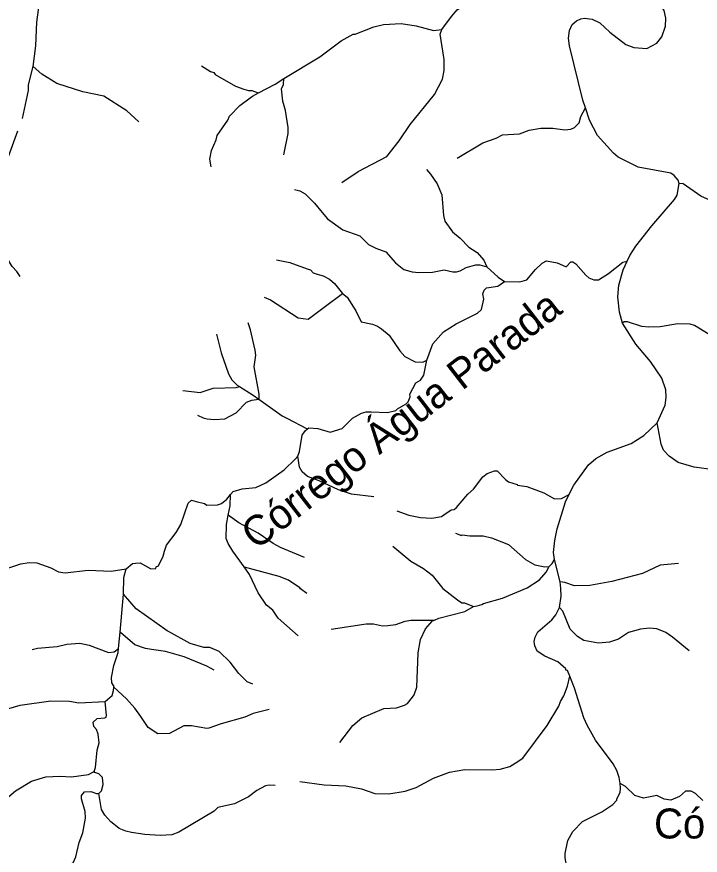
# Model space of a CAD drawing. Extents: x 393 to 446.6, y 8175.5 to 8231.
# Drawn here: x 408.07 to 412.63, y 8185.27 to 8190.87 of the extents above; entities that cross this region are included whole.
import ezdxf
from ezdxf.enums import TextEntityAlignment as Align

# ---------------------------------------------------------------- set-up
doc = ezdxf.new("R2010")
doc.units = 0
doc.header["$LTSCALE"] = 0.064
doc.linetypes.add('LONG_DASHED', pattern=[7.5, 6, -1.5])
doc.layers.add('61', color=7, linetype='Continuous')
doc.layers.add('7', color=7, linetype='Continuous', lineweight=25)
doc.layers.add('9', color=7, linetype='LONG_DASHED', lineweight=25)

msp = doc.modelspace()

# ---------------------------------------------------------------- linework, layer by layer
at = {"layer": '7'}
msp.add_line((411.6931, 8187.0939), (411.6559, 8187.2417), dxfattribs=at)
for points in [[(411.8626, 8190.2594), (411.8458, 8190.3093), (411.757, 8190.6727), (411.7505, 8190.7244), (411.757, 8190.7761), (411.7748, 8190.8148), (411.8039, 8190.839), (411.8329, 8190.8536), (411.8555, 8190.8568), (411.9072, 8190.8519), (411.9589, 8190.8277), (412.025, 8190.7647), (412.1333, 8190.6808), (412.1849, 8190.6614), (412.2721, 8190.6549), (412.3399, 8190.6904), (412.3739, 8190.7325), (412.3981, 8190.8051), (412.3997, 8190.8568), (412.3884, 8190.9085), (412.3604, 8190.9515)], [(411.0056, 8189.9223), (411.1773, 8190.0251), (411.2677, 8190.0574), (411.3081, 8190.0784), (411.4228, 8190.0849), (411.4874, 8190.1091), (411.5649, 8190.122), (411.6456, 8190.122), (411.7263, 8190.1123), (411.7651, 8190.1156), (411.7893, 8190.1285), (411.82, 8190.1592), (411.8313, 8190.2012), (411.8626, 8190.2594)], [(412.4884, 8189.7544), (412.4826, 8189.7765), (412.4558, 8189.8073), (412.4336, 8189.8217), (412.214, 8189.8637), (412.0816, 8189.9299), (412.0493, 8189.9557), (411.9427, 8190.0752), (411.891, 8190.1754), (411.8626, 8190.2594)], [(412.1415, 8189.2349), (412.1594, 8189.2722), (412.1995, 8189.3357), (412.306, 8189.4697), (412.4578, 8189.6457), (412.4756, 8189.6748), (412.4884, 8189.7544)], [(412.1106, 8188.8205), (412.0896, 8188.8932), (412.0784, 8188.9966), (412.0864, 8189.0741), (412.1139, 8189.1774), (412.1415, 8189.2349)], [(413.0772, 8188.4153), (412.9907, 8188.4734), (412.9229, 8188.5412), (412.8599, 8188.5912), (412.7436, 8188.7124), (412.7081, 8188.7398), (412.6888, 8188.7446), (412.5919, 8188.8044), (412.5628, 8188.8141), (412.4788, 8188.8157), (412.3626, 8188.7963), (412.2851, 8188.7947), (412.2398, 8188.7995), (412.1432, 8188.83), (412.1222, 8188.83), (412.1106, 8188.8205)], [(412.3416, 8188.1545), (412.3949, 8188.2731), (412.4029, 8188.3248), (412.3997, 8188.3765), (412.3723, 8188.454), (412.2964, 8188.5638), (412.1995, 8188.6801), (412.1106, 8188.8205)], [(411.7528, 8187.6744), (411.7845, 8187.7386), (411.883, 8187.8743), (411.9314, 8187.9162), (412.0073, 8187.9599), (412.1688, 8188.018), (412.2527, 8188.0697), (412.3416, 8188.1545)], [(413.5273, 8187.5871), (413.4138, 8187.6337), (413.2992, 8187.6692), (413.1377, 8187.7015), (413.0699, 8187.7079), (413.0246, 8187.7192), (413.002, 8187.7176), (412.9568, 8187.7289), (412.7663, 8187.8258), (412.721, 8187.8403), (412.5886, 8187.8597), (412.4816, 8187.8904), (412.4223, 8187.9324), (412.3835, 8187.9728), (412.3674, 8188.0115), (412.3416, 8188.1545)], [(410.6046, 8187.5674), (410.6832, 8187.5384), (410.7607, 8187.5238), (410.8382, 8187.5174), (410.9028, 8187.5303), (410.9175, 8187.5405), (410.9658, 8187.5739), (410.9867, 8187.5771), (411.0013, 8187.59), (411.0772, 8187.6789), (411.116, 8187.7128), (411.1789, 8187.7952), (411.2064, 8187.8177), (411.2548, 8187.8339), (411.2742, 8187.8355), (411.3291, 8187.7758), (411.3501, 8187.7612), (411.4066, 8187.7434), (411.4082, 8187.7386), (411.4712, 8187.7289), (411.5842, 8187.6869), (411.6553, 8187.6482), (411.7037, 8187.6498), (411.7505, 8187.6732), (411.7528, 8187.6744)], [(411.6559, 8187.2417), (411.65, 8187.2894), (411.6585, 8187.3689), (411.6747, 8187.4464), (411.7296, 8187.6272), (411.7528, 8187.6744)], [(410.9946, 8187.4174), (411.0354, 8187.4034), (411.04, 8187.4076), (411.0901, 8187.4011), (411.1805, 8187.4011), (411.2354, 8187.3866), (411.3485, 8187.3414), (411.4631, 8187.2429), (411.5245, 8187.2057), (411.5907, 8187.1928), (411.6213, 8187.1963)], [(410.5764, 8187.331), (410.6977, 8187.2316), (410.7814, 8187.1821), (410.8398, 8187.1379), (410.9109, 8187.0491), (411.0077, 8186.9732), (411.0384, 8186.9538), (411.0562, 8186.9522), (411.1159, 8186.9273)], [(411.6213, 8187.1963), (411.6411, 8187.2149), (411.6559, 8187.2417)], [(411.1159, 8186.9273), (411.1389, 8186.9331), (411.1718, 8186.9413), (411.1821, 8186.949), (411.3097, 8186.9829), (411.4744, 8187.0539), (411.5568, 8187.1072), (411.6004, 8187.1573), (411.6213, 8187.1963)], [(412.4838, 8187.2162), (412.3609, 8187.2041), (412.2431, 8187.1492), (412.0396, 8187.0943), (411.8911, 8187.0685), (411.7909, 8187.0668), (411.7263, 8187.0894), (411.6931, 8187.0939)], [(411.6906, 8186.9226), (411.7005, 8186.9975), (411.6989, 8187.0491), (411.6931, 8187.0939)], [(410.8544, 8186.8375), (410.885, 8186.8505), (411.0578, 8186.8957), (411.1159, 8186.9273)], [(411.7581, 8186.4624), (411.7427, 8186.5012), (411.7328, 8186.5033), (411.7328, 8186.513), (411.6795, 8186.5598), (411.5907, 8186.597), (411.5406, 8186.6308), (411.5245, 8186.6648), (411.5212, 8186.6939), (411.5261, 8186.7229), (411.5454, 8186.7584), (411.6391, 8186.8392), (411.665, 8186.8731), (411.6906, 8186.9226)], [(412.5547, 8186.6325), (412.4433, 8186.7245), (412.3997, 8186.7536), (412.34, 8186.7794), (412.2915, 8186.7843), (412.2302, 8186.7778), (412.1494, 8186.7536), (412.0837, 8186.7103), (412.0235, 8186.689), (411.9492, 8186.6842), (411.8523, 8186.7003), (411.8103, 8186.7277), (411.7618, 8186.7778), (411.7118, 8186.8973), (411.6906, 8186.9226)], [(410.1642, 8186.7769), (410.399, 8186.8133), (410.4474, 8186.8133), (410.5088, 8186.7988), (410.5443, 8186.8004), (410.596, 8186.8085), (410.659, 8186.8311), (410.6961, 8186.8375), (410.8544, 8186.8375)], [(410.222, 8186.019), (410.3101, 8186.1335), (410.3699, 8186.1852), (410.5168, 8186.2481), (410.6008, 8186.2514), (410.6541, 8186.2691), (410.6751, 8186.2804), (410.709, 8186.3224), (410.7203, 8186.3386), (410.7364, 8186.3903), (410.7461, 8186.6164), (410.7464, 8186.6184), (410.7607, 8186.7068), (410.7946, 8186.7794), (410.8421, 8186.8323), (410.8544, 8186.8375)], [(409.9559, 8185.7602), (410.118, 8185.7363), (410.2633, 8185.7314), (410.3667, 8185.7104), (410.4571, 8185.6797), (410.5508, 8185.6765), (410.659, 8185.6943), (410.7316, 8185.7201), (410.8479, 8185.7815), (410.9545, 8185.8219), (411.0578, 8185.8396), (411.2419, 8185.838), (411.2936, 8185.8428), (411.3582, 8185.859), (411.3933, 8185.8818), (411.4454, 8185.9155), (411.6084, 8186.1335), (411.6859, 8186.2627), (411.6956, 8186.2934), (411.7182, 8186.3322), (411.7425, 8186.3967), (411.7581, 8186.4624)], [(412.0939, 8185.7472), (412.0891, 8185.7866), (412.0719, 8185.8332), (412.0477, 8185.8768), (411.9298, 8186.0366), (411.8733, 8186.1352), (411.8523, 8186.1836), (411.7893, 8186.3838), (411.7581, 8186.4624)], [(411.8612, 8184.6542), (411.8344, 8184.6949), (411.8006, 8184.8207), (411.7812, 8185.0339), (411.7457, 8185.1534), (411.7279, 8185.2502), (411.7279, 8185.2793), (411.7457, 8185.3665), (411.778, 8185.4246), (411.8426, 8185.4924), (411.9718, 8185.557), (412.046, 8185.6055), (412.0719, 8185.6345), (412.0719, 8185.6442), (412.0945, 8185.6862), (412.0977, 8185.7153), (412.0939, 8185.7472)], [(412.6468, 8185.6329), (412.5967, 8185.6797), (412.5693, 8185.6959), (412.5305, 8185.6943), (412.4901, 8185.6588), (412.4336, 8185.6345), (412.3884, 8185.6426), (412.34, 8185.6652), (412.2511, 8185.6475), (412.193, 8185.6652), (412.13, 8185.725), (412.095, 8185.7465), (412.0939, 8185.7472)]]:
    msp.add_lwpolyline(points, dxfattribs=at)
at = {"layer": '9'}
for p, q in [((408.7562, 8186.7561), (408.7795, 8187.0107)), ((408.7463, 8186.6484), (408.7562, 8186.7561))]:
    msp.add_line(p, q, dxfattribs=at)
for points in [[(410.9033, 8190.7814), (410.9675, 8190.8689), (411.0061, 8190.9133), (411.0368, 8190.9359), (411.0788, 8190.9925), (411.103, 8191.1297), (411.1498, 8191.1684), (411.1691, 8191.2413), (411.1854, 8191.2705), (411.2519, 8191.3416), (411.2718, 8191.3789), (411.2887, 8191.4349), (411.2952, 8191.5189), (411.3722, 8191.6951)], [(408.1751, 8190.5341), (408.1756, 8190.536), (408.1931, 8190.6736), (408.2012, 8190.831), (408.227, 8191.0247), (408.2481, 8191.1232), (408.2635, 8191.1731), (408.2884, 8191.254), (408.3385, 8191.3816), (408.4128, 8191.4962), (408.4692, 8191.5543), (408.4694, 8191.5545)], [(409.85, 8190.4547), (410.0889, 8190.5984), (410.2326, 8190.7066), (410.3118, 8190.7518), (410.3247, 8190.7518), (410.4507, 8190.8002), (410.5152, 8190.8148), (410.6315, 8190.8229), (410.7316, 8190.8067), (410.8479, 8190.776), (410.9033, 8190.7814)], [(410.2356, 8189.7609), (410.3457, 8189.8346), (410.5362, 8189.9347), (410.6202, 8190.0381), (410.6928, 8190.1479), (410.856, 8190.3481), (410.9076, 8190.4499), (410.9189, 8190.508), (410.9189, 8190.5823), (410.8931, 8190.7502), (410.9033, 8190.7814)], [(408.0879, 8189.1316), (408.0669, 8189.1655), (408.0365, 8189.1984), (407.9994, 8189.2598), (407.9654, 8189.3324), (407.9251, 8189.4616), (407.9105, 8189.6102), (407.9219, 8189.6812), (407.9396, 8189.7442), (408.1043, 8190.1883), (408.1447, 8190.3756), (408.1447, 8190.4127), (408.1751, 8190.5341)], [(408.8814, 8190.1645), (408.8019, 8190.2399), (408.6485, 8190.3368), (408.508, 8190.3659), (408.3336, 8190.4224), (408.2335, 8190.4837), (408.1751, 8190.5341)], [(409.3005, 8190.5392), (409.3589, 8190.5007), (409.3817, 8190.4951), (409.3914, 8190.4805), (409.527, 8190.403), (409.582, 8190.3846), (409.6142, 8190.3739), (409.6352, 8190.3739), (409.6773, 8190.3599), (409.6811, 8190.3586)], [(409.6811, 8190.3586), (409.7918, 8190.4175), (409.85, 8190.4547)], [(409.8483, 8189.9443), (409.8508, 8189.9562), (409.879, 8190.0882), (409.879, 8190.1269), (409.8612, 8190.24), (409.8419, 8190.3029), (409.8338, 8190.3853), (409.8461, 8190.4141), (409.85, 8190.4547)], [(409.3637, 8189.8656), (409.3558, 8189.917), (409.3671, 8189.9735), (409.3978, 8190.0445), (409.4043, 8190.0736), (409.4753, 8190.177), (409.4866, 8190.2028), (409.5544, 8190.2738), (409.6239, 8190.325), (409.64, 8190.3368), (409.6811, 8190.3586)], [(410.8012, 8189.8466), (410.8285, 8189.8168), (410.8737, 8189.7507), (410.9044, 8189.678), (410.9141, 8189.5391), (410.9238, 8189.502), (410.9755, 8189.4309), (411.0271, 8189.3889), (411.0836, 8189.3292), (411.1402, 8189.2921), (411.1837, 8189.2404), (411.205, 8189.1978)], [(409.921, 8189.7125), (409.9549, 8189.7044), (409.9551, 8189.7043), (409.9921, 8189.6844), (410.055, 8189.6215), (410.1046, 8189.5607), (410.1406, 8189.5165), (410.244, 8189.4438), (410.357, 8189.4035), (410.4135, 8189.347), (410.4636, 8189.3211), (410.5298, 8189.2969), (410.5944, 8189.2242), (410.6493, 8189.179), (410.7058, 8189.1628), (410.751, 8189.158), (410.8414, 8189.1612), (410.9205, 8189.1758), (410.9771, 8189.1628), (411.0029, 8189.1628), (411.0271, 8189.1693), (411.0659, 8189.1919), (411.1321, 8189.2113), (411.1579, 8189.2097), (411.205, 8189.1978)], [(413.201, 8189.6554), (413.1816, 8189.6566), (413.1151, 8189.7068), (413.0731, 8189.715), (413.0246, 8189.6899), (413.0004, 8189.6618), (412.9552, 8189.6376), (412.8761, 8189.6505), (412.826, 8189.6893), (412.8147, 8189.6893), (412.7404, 8189.6311), (412.7178, 8189.6311), (412.6339, 8189.6683), (412.5144, 8189.7522), (412.4884, 8189.7544)], [(409.8006, 8189.2444), (409.8903, 8189.2259), (410.0041, 8189.1845), (410.0276, 8189.1758), (410.0453, 8189.1564), (410.0722, 8189.1485), (410.1116, 8189.137), (410.1535, 8189.1144), (410.1874, 8189.0854), (410.2405, 8189.0195)], [(411.205, 8189.1978), (411.2809, 8189.1278), (411.3231, 8189.0993)], [(411.3231, 8189.0993), (411.4246, 8189.0958), (411.4719, 8189.1103), (411.5291, 8189.1792), (411.5746, 8189.221), (411.6036, 8189.2372), (411.6747, 8189.2226), (411.7296, 8189.1984), (411.736, 8189.1984), (411.7643, 8189.2304), (411.7795, 8189.2304), (411.7993, 8189.2176), (411.8652, 8189.1419), (411.8852, 8189.1238), (411.9178, 8189.1107), (411.9427, 8189.1112), (411.9508, 8189.1112), (412.017, 8189.1516), (412.1123, 8189.2274), (412.1415, 8189.2349)], [(410.8039, 8188.5733), (410.8436, 8188.6829), (410.9157, 8188.7624), (410.9997, 8188.8173), (411.1418, 8188.8867), (411.1692, 8188.911), (411.1837, 8188.9804), (411.1773, 8189.0159), (411.187, 8189.0417), (411.2015, 8189.0563), (411.279, 8189.0676), (411.3231, 8189.0993)], [(409.7174, 8188.9942), (409.7594, 8188.9767), (409.9452, 8188.8561), (410.0114, 8188.8463), (410.1275, 8188.9341), (410.2405, 8189.0195)], [(410.2405, 8189.0195), (410.273, 8188.9949), (410.3295, 8188.9029), (410.3651, 8188.8302), (410.4404, 8188.8133), (410.4749, 8188.8011), (410.5023, 8188.7818), (410.5524, 8188.7414), (410.6234, 8188.6349), (410.6574, 8188.5977), (410.7251, 8188.5621), (410.7769, 8188.5604), (410.8039, 8188.5733)], [(409.6826, 8188.313), (409.6836, 8188.3132), (409.6852, 8188.3474), (409.6513, 8188.5299), (409.6626, 8188.6074), (409.6578, 8188.6413), (409.6269, 8188.7762), (409.6106, 8188.8228)], [(409.4, 8188.748), (409.4317, 8188.6219), (409.4801, 8188.4831), (409.5028, 8188.4427), (409.5383, 8188.4071), (409.5537, 8188.3974)], [(410.0075, 8188.114), (410.0163, 8188.1208), (410.0764, 8188.1167), (410.1584, 8188.0923), (410.2391, 8188.1165), (410.3069, 8188.1859), (410.3667, 8188.2198), (410.399, 8188.2295), (410.4331, 8188.2279), (410.5411, 8188.223), (410.5976, 8188.2376), (410.6073, 8188.2489), (410.667, 8188.2828), (410.6799, 8188.2957), (410.6928, 8188.328), (410.6912, 8188.3474), (410.73, 8188.4217), (410.7607, 8188.4394), (410.7849, 8188.4734), (410.8039, 8188.5733)], [(409.1754, 8188.3716), (409.2896, 8188.3571), (409.3784, 8188.3861), (409.5302, 8188.391), (409.5529, 8188.3972), (409.5537, 8188.3974)], [(409.5537, 8188.3974), (409.6451, 8188.34), (409.6826, 8188.313)], [(409.272, 8188.2052), (409.3106, 8188.1875), (409.3364, 8188.1827), (409.3865, 8188.1763), (409.4559, 8188.1811), (409.5318, 8188.2214), (409.5996, 8188.2925), (409.6352, 8188.3054), (409.6826, 8188.313)], [(409.6826, 8188.313), (409.837, 8188.202), (409.8691, 8188.1855), (410.0058, 8188.1149), (410.0075, 8188.114)], [(409.9416, 8187.9318), (409.9532, 8187.9645), (409.9719, 8188.0729), (409.9918, 8188.1021), (410.0075, 8188.114)], [(409.4939, 8187.6759), (409.5108, 8187.6966), (409.5706, 8187.7144), (409.6626, 8187.7241), (409.7288, 8187.7532), (409.8516, 8187.842), (409.9258, 8187.9114), (409.9416, 8187.9318)], [(410.451, 8187.6608), (410.301, 8187.6777), (410.2133, 8187.708), (410.0841, 8187.7677), (410.0065, 8187.7961), (409.9726, 8187.8276), (409.9528, 8187.8591), (409.9416, 8187.9318)], [(408.797, 8187.1798), (408.8379, 8187.2148), (408.8585, 8187.2186), (408.8891, 8187.2203), (408.9602, 8187.1799), (408.9941, 8187.1831), (408.9973, 8187.1928), (409.0119, 8187.1993), (409.0441, 8187.2655), (409.0535, 8187.298), (409.0652, 8187.3382), (409.1297, 8187.4221), (409.1604, 8187.4754), (409.2105, 8187.6175), (409.2331, 8187.6385), (409.264, 8187.6305), (409.3203, 8187.6159), (409.3348, 8187.6062), (409.4059, 8187.6078), (409.4333, 8187.6165), (409.4683, 8187.6445), (409.4939, 8187.6759)], [(409.4785, 8187.5385), (409.4898, 8187.6014), (409.4939, 8187.6759)], [(409.5834, 8187.1928), (409.5076, 8187.2978), (409.4769, 8187.3495), (409.464, 8187.3834), (409.4672, 8187.4754), (409.4785, 8187.5385)], [(409.9882, 8187.2557), (409.8259, 8187.3234), (409.7773, 8187.3495), (409.6788, 8187.4173), (409.548, 8187.4867), (409.4786, 8187.5384), (409.4785, 8187.5385)], [(407.7629, 8187.1275), (407.8331, 8187.1234), (407.8961, 8187.1379), (407.9929, 8187.1799), (408.0931, 8187.2122), (408.148, 8187.2219), (408.2012, 8187.2203), (408.2933, 8187.1863), (408.345, 8187.1605), (408.3886, 8187.1525), (408.542, 8187.1702), (408.697, 8187.1654), (408.797, 8187.1798)], [(409.9452, 8186.7333), (409.8116, 8186.8506), (409.7797, 8186.8977), (409.7756, 8186.9038), (409.7337, 8186.9377), (409.6787, 8187.0201), (409.6206, 8187.1412), (409.5834, 8187.1928)], [(410.0018, 8187.0161), (409.9609, 8187.0452), (409.9565, 8187.054), (409.8806, 8187.104), (409.8177, 8187.1282), (409.5876, 8187.1916), (409.5834, 8187.1928)], [(408.7795, 8187.0107), (408.7801, 8187.1221), (408.797, 8187.1798)], [(409.6426, 8186.4089), (409.6053, 8186.4253), (409.5492, 8186.4801), (409.4898, 8186.5566), (409.4172, 8186.6276), (409.3542, 8186.6535), (409.3154, 8186.6551), (409.2234, 8186.6809), (409.0781, 8186.7617), (409.0709, 8186.7667), (408.8628, 8186.9124), (408.7795, 8187.0107)], [(409.3833, 8186.5026), (409.3343, 8186.5294), (409.183, 8186.5921), (409.0587, 8186.6276), (408.965, 8186.6421), (408.9252, 8186.6482), (408.8551, 8186.6727), (408.7579, 8186.7547), (408.7562, 8186.7561)], [(408.17, 8186.6417), (408.2039, 8186.6511), (408.3353, 8186.6615), (408.3999, 8186.6777), (408.4871, 8186.6825), (408.5484, 8186.6696), (408.6792, 8186.6212), (408.7164, 8186.626), (408.745, 8186.6474), (408.7463, 8186.6484)], [(408.7145, 8186.3886), (408.7153, 8186.3949), (408.7001, 8186.4182), (408.6989, 8186.4544), (408.7141, 8186.5337), (408.7439, 8186.6218), (408.7463, 8186.6484)], [(408.6574, 8186.2928), (408.7036, 8186.3342), (408.7118, 8186.3669), (408.7145, 8186.3886)], [(409.7518, 8186.2414), (409.6449, 8186.2127), (409.5884, 8186.1884), (409.4301, 8186.1448), (409.3494, 8186.1157), (409.3348, 8186.1125), (409.2331, 8186.1303), (409.1814, 8186.1303), (409.0861, 8186.0802), (409.0086, 8186.077), (408.9424, 8186.1206), (408.8934, 8186.1932), (408.8552, 8186.2498), (408.7987, 8186.3111), (408.7145, 8186.3886)], [(407.6511, 8186.1139), (407.7024, 8186.1127), (407.7975, 8186.1432), (407.9606, 8186.2304), (408.0898, 8186.2691), (408.2933, 8186.2982), (408.4192, 8186.295), (408.4806, 8186.2853), (408.6574, 8186.2928)], [(408.5827, 8185.8262), (408.5921, 8185.8519), (408.602, 8185.968), (408.616, 8186.0169), (408.609, 8186.0764), (408.5985, 8186.1068), (408.5804, 8186.1272), (408.5769, 8186.1552), (408.6026, 8186.1809), (408.6539, 8186.1844), (408.664, 8186.1887), (408.6651, 8186.1997), (408.6574, 8186.2928)], [(407.2495, 8185.4007), (407.2903, 8185.424), (407.3373, 8185.4408), (407.4504, 8185.4521), (407.586, 8185.4488), (407.6441, 8185.4585), (407.6506, 8185.4682), (407.7766, 8185.494), (407.8831, 8185.5506), (408.0575, 8185.6975), (408.1641, 8185.7621), (408.2594, 8185.7912), (408.3547, 8185.7944), (408.4305, 8185.7896), (408.5452, 8185.8057), (408.5827, 8185.8262)], [(408.6131, 8185.6804), (408.6317, 8185.6979), (408.6434, 8185.7399), (408.6387, 8185.7866), (408.6142, 8185.811), (408.5874, 8185.8192), (408.5827, 8185.8262)], [(409.7923, 8185.7322), (409.7514, 8185.7346), (409.7272, 8185.7298), (409.6691, 8185.6991), (409.6142, 8185.6571), (409.5205, 8185.6103), (409.4091, 8185.5861), (409.3833, 8185.5619), (409.1491, 8185.4214), (409.1023, 8185.4036), (409.0232, 8185.3988), (408.9214, 8185.4053), (408.8326, 8185.4198), (408.7939, 8185.4278), (408.7503, 8185.4456), (408.7247, 8185.466), (408.6937, 8185.4908), (408.6533, 8185.5344), (408.6324, 8185.5716), (408.6131, 8185.6804)], [(408.2609, 8185.0541), (408.2656, 8185.1101), (408.2749, 8185.1416), (408.2901, 8185.1696), (408.3006, 8185.1824), (408.3191, 8185.1905), (408.3789, 8185.1921), (408.4418, 8185.2163), (408.4596, 8185.2567), (408.4822, 8185.3519), (408.5064, 8185.4166), (408.5242, 8185.5151), (408.5226, 8185.5587), (408.4983, 8185.6443), (408.4983, 8185.6668), (408.5177, 8185.691), (408.5597, 8185.6927), (408.5991, 8185.6792), (408.6131, 8185.6804)]]:
    msp.add_lwpolyline(points, dxfattribs=at)

# ---------------------------------------------------------------- texts
at = {"layer": '61'}
msp.add_text('Córrego Água Parada', height=0.2, rotation=37.798, dxfattribs=at).set_placement((410.6923, 8188.0981), align=Align.CENTER)
msp.add_text('Córregão', height=0.2, dxfattribs=at).set_placement((412.8784, 8185.379), align=Align.CENTER)

doc.saveas('drawing.dxf')
